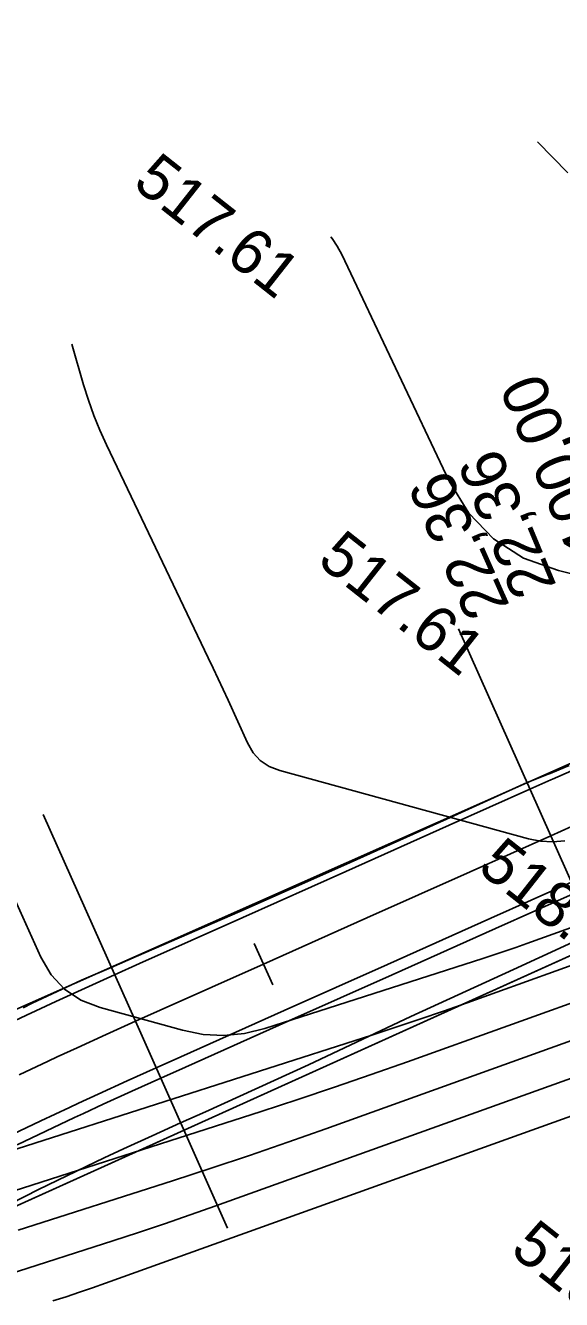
# Model space of a CAD drawing. Extents: x -636600 to -628587, y -1090963 to -1085869.
# Drawn here: x -629625.6 to -629601.9, y -1089681.8 to -1089625.5 of the extents above; entities that cross this region are included whole.
import ezdxf

# ---------------------------------------------------------------- set-up
doc = ezdxf.new("R2010")
doc.units = 0
for name, color, linetype in [('01_PARCELY_NÁVRH_PC', 7, 'Continuous'), ('21', 7, 'Continuous'), ('dno příkopu', 7, 'Continuous'), ('Ex_Major Contours', 7, 'Continuous'), ('Ex_Minor Contours', 7, 'Continuous'), ('HEKTOMETRY20', 7, 'Continuous'), ('HL_BODY', 7, 'Continuous'), ('koty_vše', 7, 'Continuous'), ('PARCELY_NÁVRH_SILNICE_ŽELEZNICE', 7, 'Continuous'), ('POLOMERY', 7, 'Continuous'), ('situace_osa', 7, 'Continuous'), ('situace_těleso', 7, 'Continuous'), ('situace_vozovka', 7, 'Continuous')]:
    doc.layers.add(name, color=color, linetype=linetype)

msp = doc.modelspace()

# ---------------------------------------------------------------- linework, layer by layer
at = {"layer": '01_PARCELY_NÁVRH_PC'}
for points in [[(-629254.654, -1089739.869), (-629360.834, -1089658.331), (-629368.291, -1089654.325), (-629380.483, -1089650.342), (-629407.529, -1089646.03), (-629420.129, -1089642.952), (-629431.224, -1089638.631), (-629441.359, -1089632.253), (-629462.999, -1089614.168), (-629469.387, -1089611.971), (-629476.142, -1089612.42), (-629540.496, -1089642.406), (-629554.39, -1089646.509), (-629581.677, -1089651.277), (-629593.36, -1089654.473), (-629629.454, -1089670.47), (-629647.363, -1089680.417), (-629666.288, -1089692.668)], [(-629669.229, -1089703.189), (-629636.498, -1089682.368), (-629594.828, -1089663.555), (-629566.208, -1089655.26), (-629543.029, -1089650.823), (-629502.778, -1089630.854), (-629477.842, -1089619.529), (-629472.37, -1089618.387), (-629466.831, -1089619.344), (-629458.171, -1089625.363), (-629433.235, -1089646.243), (-629378.586, -1089656.962), (-629364.857, -1089662.954), (-629248.799, -1089751.038)]]:
    msp.add_lwpolyline(points, dxfattribs=at)
at = {"layer": '21'}
msp.add_line((-629594.828, -1089663.555), (-629636.498, -1089682.368), dxfattribs=at)
at = {"layer": 'dno příkopu'}
msp.add_lwpolyline([(-629601.243, -1089663.782), (-629604.812, -1089665.375), (-629609.378, -1089667.414), (-629613.943, -1089669.452), (-629618.509, -1089671.49), (-629619.609, -1089671.981), (-629620.885, -1089672.555), (-629622.158, -1089673.136), (-629623.025, -1089673.537), (-629623.427, -1089673.725), (-629624.694, -1089674.32), (-629625.957, -1089674.923)], dxfattribs=at)
at = {"layer": 'Ex_Major Contours'}
for points in [[(-629593.669, -1089651.637), (-629602.017, -1089649.563), (-629603.574, -1089649.005), (-629604.899, -1089648.16), (-629605.989, -1089647.03), (-629606.847, -1089645.614), (-629611.603, -1089635.603), (-629611.799, -1089635.235), (-629612.029, -1089634.891), (-629612.091, -1089634.815)], [(-629598.825, -1089669.383), (-629612.306, -1089674.215), (-629613.994, -1089674.812), (-629615.686, -1089675.394), (-629617.384, -1089675.962), (-629619.086, -1089676.515), (-629625.905, -1089678.7)]]:
    msp.add_lwpolyline(points, dxfattribs=at)
at = {"layer": 'Ex_Minor Contours'}
for points in [[(-629601.601, -1089631.991), (-629602.942, -1089630.618)], [(-629601.74, -1089661.497), (-629602.277, -1089661.543), (-629602.815, -1089661.512), (-629603.354, -1089661.403), (-629614.346, -1089658.394), (-629614.811, -1089658.215), (-629615.204, -1089657.953), (-629615.525, -1089657.606), (-629615.775, -1089657.176), (-629616.633, -1089655.287), (-629616.848, -1089654.816), (-629617.066, -1089654.345), (-629617.286, -1089653.876), (-629617.509, -1089653.407), (-629622.003, -1089644.012), (-629622.297, -1089643.363), (-629622.564, -1089642.703), (-629622.803, -1089642.033), (-629623.015, -1089641.352), (-629623.533, -1089639.555)], [(-629601.486, -1089665.344), (-629603.42, -1089666.038), (-629603.905, -1089666.209), (-629604.391, -1089666.376), (-629604.878, -1089666.539), (-629605.366, -1089666.698), (-629615.006, -1089669.786), (-629615.91, -1089670.008), (-629616.816, -1089670.094), (-629617.725, -1089670.046), (-629618.638, -1089669.864), (-629622.292, -1089668.863), (-629623.141, -1089668.537), (-629623.859, -1089668.057), (-629624.446, -1089667.424), (-629624.903, -1089666.638), (-629627.446, -1089661.036)], [(-629600.816, -1089666.768), (-629606.056, -1089668.647), (-629607.105, -1089669.018), (-629608.157, -1089669.379), (-629609.212, -1089669.732), (-629610.27, -1089670.076), (-629630.157, -1089676.447)], [(-629626.928, -1089677.22), (-629615.173, -1089673.455), (-629613.546, -1089672.926), (-629611.923, -1089672.383), (-629610.305, -1089671.826), (-629608.691, -1089671.255), (-629599.821, -1089668.075)], [(-629626.314, -1089680.638), (-629621.731, -1089679.17), (-629620.587, -1089678.798), (-629619.446, -1089678.417), (-629618.308, -1089678.025), (-629617.174, -1089677.624), (-629597.83, -1089670.69)], [(-629596.834, -1089671.997), (-629622.042, -1089681.033), (-629622.623, -1089681.239), (-629623.206, -1089681.439), (-629623.79, -1089681.635), (-629624.376, -1089681.825)]]:
    msp.add_lwpolyline(points, dxfattribs=at)
at = {"layer": 'HEKTOMETRY20'}
msp.add_lwpolyline([(-629614.657, -1089667.854), (-629615.472, -1089666.028)], dxfattribs=at)
at = {"layer": 'HL_BODY'}
for points in [[(-629602.364, -1089661.271), (-629598.288, -1089670.402)], [(-629620.73, -1089669.47), (-629616.653, -1089678.601)]]:
    msp.add_lwpolyline(points, dxfattribs=at)
at = {"layer": 'PARCELY_NÁVRH_SILNICE_ŽELEZNICE'}
msp.add_lwpolyline([(-629239.774, -1089757.887), (-629364.857, -1089662.954), (-629378.586, -1089656.962), (-629444.439, -1089644.045), (-629521.798, -1089646.759), (-629566.208, -1089655.26), (-629594.828, -1089663.555), (-629636.498, -1089682.368), (-629669.229, -1089703.189)], dxfattribs=at)
at = {"layer": 'POLOMERY'}
for points in [[(-629602.364, -1089661.271), (-629606.441, -1089652.14)], [(-629620.73, -1089669.47), (-629624.806, -1089660.339)]]:
    msp.add_lwpolyline(points, dxfattribs=at)
at = {"layer": 'situace_osa'}
msp.add_lwpolyline([(-629601.451, -1089660.864), (-629602.364, -1089661.271), (-629605.933, -1089662.864), (-629610.499, -1089664.902), (-629615.065, -1089666.941), (-629619.63, -1089668.979), (-629620.73, -1089669.47), (-629622.02, -1089670.05), (-629623.307, -1089670.638), (-629624.184, -1089671.043), (-629624.591, -1089671.233), (-629625.871, -1089671.835)], dxfattribs=at)
at = {"layer": 'situace_těleso'}
for points in [[(-629625.695, -1089668.87), (-629625.286, -1089668.673), (-629624.406, -1089668.251), (-629623.105, -1089667.656), (-629621.794, -1089667.087), (-629620.688, -1089666.61), (-629616.103, -1089664.614), (-629611.532, -1089662.589), (-629606.972, -1089660.537), (-629603.411, -1089658.927), (-629602.481, -1089658.552), (-629602.395, -1089658.517), (-629601.546, -1089658.175)], [(-629600.455, -1089665.548), (-629604.006, -1089667.182), (-629608.552, -1089669.263), (-629613.075, -1089671.397), (-629617.626, -1089673.47), (-629618.726, -1089673.96), (-629619.992, -1089674.524), (-629621.254, -1089675.101), (-629622.112, -1089675.502), (-629622.51, -1089675.69), (-629623.76, -1089676.29), (-629625.005, -1089676.903), (-629626.244, -1089677.527)]]:
    msp.add_lwpolyline(points, dxfattribs=at)
at = {"layer": 'situace_vozovka'}
for points in [[(-629601.446, -1089658.4), (-629602.282, -1089658.771), (-629602.366, -1089658.808), (-629603.282, -1089659.217), (-629606.85, -1089660.81), (-629611.416, -1089662.848), (-629615.982, -1089664.886), (-629620.547, -1089666.924), (-629621.647, -1089667.415), (-629622.949, -1089668.001), (-629624.248, -1089668.594), (-629625.132, -1089669.003), (-629625.543, -1089669.194), (-629626.835, -1089669.802)], [(-629601.446, -1089658.4), (-629602.282, -1089658.771), (-629602.366, -1089658.808), (-629603.282, -1089659.217), (-629606.85, -1089660.81), (-629611.416, -1089662.848), (-629615.982, -1089664.886), (-629620.547, -1089666.924), (-629621.647, -1089667.415), (-629622.949, -1089668.001), (-629624.248, -1089668.594), (-629625.132, -1089669.003), (-629625.543, -1089669.194), (-629626.835, -1089669.802)], [(-629601.447, -1089663.326), (-629605.016, -1089664.919), (-629609.582, -1089666.957), (-629614.147, -1089668.995), (-629618.713, -1089671.034), (-629619.813, -1089671.524), (-629621.091, -1089672.1), (-629622.367, -1089672.682), (-629623.236, -1089673.084), (-629623.639, -1089673.272), (-629624.908, -1089673.869), (-629626.173, -1089674.473)], [(-629601.447, -1089663.326), (-629605.016, -1089664.919), (-629609.582, -1089666.957), (-629614.147, -1089668.995), (-629618.713, -1089671.034), (-629619.813, -1089671.524), (-629621.091, -1089672.1), (-629622.367, -1089672.682), (-629623.236, -1089673.084), (-629623.639, -1089673.272), (-629624.908, -1089673.869), (-629626.173, -1089674.473)]]:
    msp.add_lwpolyline(points, dxfattribs=at)

# ---------------------------------------------------------------- texts
at = {"layer": 'koty_vše'}
for s, p in [('517.61', (-629620.911, -1089632.557)), ('517.61', (-629612.75, -1089649.224)), ('518.07', (-629605.667, -1089662.787)), ('519.56', (-629604.219, -1089679.685))]:
    msp.add_text(s, height=2, rotation=321.7265, dxfattribs=at).set_placement(p)
at = {"layer": 'POLOMERY'}
for s, rotation, p in [('-100,00', 112.6249, (-629599.321, -1089649.079)), ('22,36', 112.6249, (-629602.091, -1089650.233)), ('22,36', 114.0573, (-629604.158, -1089651.121))]:
    msp.add_text(s, height=2, rotation=rotation, dxfattribs=at).set_placement(p)

doc.saveas('drawing.dxf')
